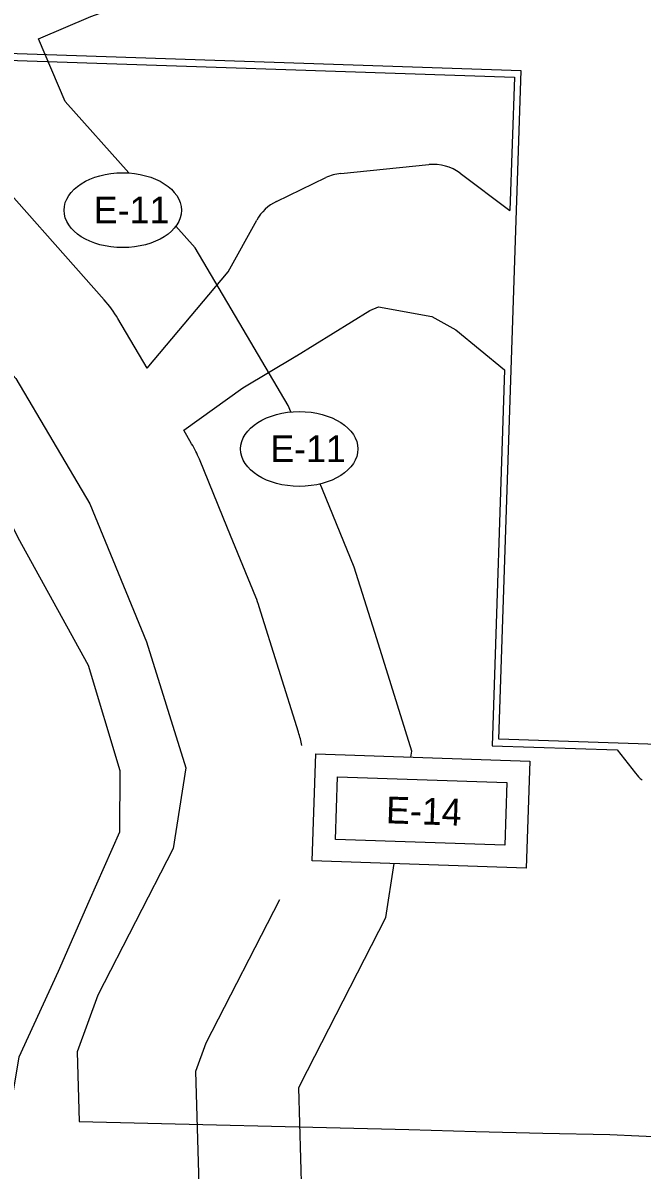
# Model space of a CAD drawing. Extents: x 977239 to 983725, y 1525948 to 1526901.
# Drawn here: x 978029.8 to 978168.6, y 1526495.3 to 1526752.6 of the extents above; entities that cross this region are included whole.
import ezdxf

# ---------------------------------------------------------------- set-up
doc = ezdxf.new("R2010")
doc.units = 0
for name, color, linetype in [('R_Erosion', 7, 'Continuous'), ('R_No Plot', 7, 'Continuous'), ('R_Water', 7, 'Continuous')]:
    doc.layers.add(name, color=color, linetype=linetype)

msp = doc.modelspace()

# ---------------------------------------------------------------- linework, layer by layer
at = {"layer": 'R_Erosion'}
for p, q in [((978010.08, 1526744.75), (978140.02, 1526740.4)), ((978140.02, 1526740.4), (978139.02, 1526710.55)), ((978101.09, 1526718.82), (978120.87, 1526720.8)), ((978086.67, 1526712.54), (978097.74, 1526717.88)), ((978057.69, 1526675.12), (978051.12, 1526686.26)), ((978137.82, 1526674.76), (978135, 1526590.48)), ((978067.66, 1526658.22), (978065.89, 1526661.22)), ((978075.71, 1526639.27), (978069.39, 1526654.73)), ((978082.04, 1526623.81), (978075.71, 1526639.27)), ((978135, 1526590.48), (978163.06, 1526589.54)), ((978163.06, 1526589.54), (978167.2, 1526584.31))]:
    msp.add_line(p, q, dxfattribs=at)
for points in [[(978048.06, 1526690.47), (978019.67, 1526722.46), (978010.08, 1526744.75)], [(978127.84, 1526718.87), (978139.02, 1526710.55)], [(978057.69, 1526675.12), (978075.86, 1526696.79), (978082.26, 1526708.37)], [(978091.16, 1526677.94), (978107.64, 1526688.12), (978109.54, 1526688.9), (978121.51, 1526686.77), (978126.86, 1526683.72), (978137.82, 1526674.76)], [(978065.89, 1526661.22), (978079.13, 1526670.72), (978091.05, 1526677.87)], [(978091.6, 1526593.56), (978087.21, 1526607.6), (978082.81, 1526621.65)], [(978080.34, 1526443.84), (978075.14, 1526454.21), (978069.68, 1526479.32), (978068.59, 1526517.53), (978070.92, 1526523.88), (978087.43, 1526556.02)]]:
    msp.add_lwpolyline(points, dxfattribs=at)
for points in [[(978095.51, 1526588.65), (978143.49, 1526587.05), (978142.69, 1526563.07), (978094.71, 1526564.67)], [(978100.34, 1526583.49), (978138.32, 1526582.22), (978137.85, 1526568.23), (978099.88, 1526569.5)]]:
    msp.add_lwpolyline(points, close=True, dxfattribs=at)
for centre, radius, start, end in [((978121.87, 1526710.85), 10, 53.3551, 95.71), ((978102.08, 1526708.87), 10, 95.71, 115.7397), ((978091.01, 1526703.53), 10, 115.7397, 151.063), ((978027.86, 1526672.55), 27, 30.5316, 41.5845), ((978085.9, 1526686.45), 10, 300.961, 301.7169), ((978044.4, 1526644.5), 27, 22.2493, 30.5285), ((978050.72, 1526629.05), 27, 22.2448, 22.2493), ((978057.05, 1526613.59), 27, 17.3714, 22.2448), ((978065.84, 1526585.49), 27, 10.8099, 17.3763), ((978175.04, 1526590.51), 10, 218.2904, 230.1585)]:
    msp.add_arc(centre, radius, start, end, dxfattribs=at)
for centre in [(978052.21, 1526710.58), (978091.79, 1526657.04)]:
    msp.add_ellipse(centre, major_axis=(13.15, 0), ratio=0.638788, dxfattribs=at)
at = {"layer": 'R_No Plot'}
for p, q in [((978141.57, 1526741.85), (977980.16, 1526747.26)), ((978136.55, 1526591.93), (978141.57, 1526741.85)), ((978338.42, 1526585.16), (978136.55, 1526591.93)), ((978042.41, 1526506.24), (978116.37, 1526504.44)), ((978116.37, 1526504.44), (978131.38, 1526503.96)), ((978131.38, 1526503.96), (978146.37, 1526503.64)), ((978146.37, 1526503.64), (978161.38, 1526503.3)), ((978161.38, 1526503.3), (978176.36, 1526502.64))]:
    msp.add_line(p, q, dxfattribs=at)
for points in [[(977962.65, 1526747.84), (977968.99, 1526733.18), (977977.19, 1526717.98), (977985.41, 1526702.75), (977999.41, 1526685.31), (978013.35, 1526667.94), (978028.7, 1526637.19), (978044.45, 1526608.56), (978051.59, 1526584.97), (978051.51, 1526571.11), (978044.63, 1526555.55), (978037.71, 1526539.89), (978028.88, 1526520.64), (978026.51, 1526506.34)], [(977980.16, 1526747.26), (977997.01, 1526708.07), (978028.27, 1526672.84), (978036.56, 1526658.78), (978044.85, 1526644.73), (978051.19, 1526629.24), (978057.52, 1526613.76), (978061.92, 1526599.69), (978066.35, 1526585.53), (978063.52, 1526567.47), (978046.6, 1526534.53), (978041.96, 1526521.86), (978042.41, 1526506.24)]]:
    msp.add_lwpolyline(points, dxfattribs=at)
for centre in [(978052.21, 1526710.58), (978091.79, 1526657.04)]:
    msp.add_ellipse(centre, major_axis=(13.15, 0), ratio=0.638788, dxfattribs=at)
at = {"layer": 'R_Water'}
for points in [[(978053.54, 1526718.94), (978039.33, 1526734.96), (978033.29, 1526749.02), (978045.03, 1526754.03), (978068.76, 1526762.53), (978118.72, 1526797.54), (978118.59, 1526858.94), (978095.26, 1526901.24)], [(978089.89, 1526665.35), (978089.31, 1526666.78), (978079.2, 1526683.92), (978068.47, 1526702.11), (978064.12, 1526707.02)], [(978116.83, 1526587.94), (978117.04, 1526589.29), (978109.16, 1526614.47), (978104.13, 1526630.55), (978097, 1526647.98), (978096.5, 1526649.2)], [(978096.51, 1526464.21), (978092.61, 1526482.11), (978091.71, 1526513.77), (978092.03, 1526514.63), (978111.2, 1526551.94), (978113.09, 1526564.05)]]:
    msp.add_lwpolyline(points, dxfattribs=at)

# ---------------------------------------------------------------- texts
at = {"layer": 'R_Erosion'}
for p in [(978045.71, 1526707.63), (978085.29, 1526654.09)]:
    msp.add_text('E-11', height=5.999, dxfattribs=at).set_placement(p)
msp.add_text('E-14', height=6, rotation=358.0901, dxfattribs=at).set_placement((978111.16, 1526573.12))

doc.saveas('drawing.dxf')
